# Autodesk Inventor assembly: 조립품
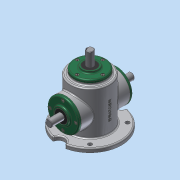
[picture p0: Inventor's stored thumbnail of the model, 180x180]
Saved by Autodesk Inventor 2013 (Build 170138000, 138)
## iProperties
Created: 2018-04
Part Number: 조립품
Document SubType Name: Assembly
Designer: dgall
Author: dgall
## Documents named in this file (16)
- C:\Users\dgall\Desktop\480407V1029\조립품.iam
- C:\Users\dgall\Desktop\480407V1029\메인 베벨기어.ipt
- C:\Users\dgall\Desktop\480407V1029\메인 축.ipt
- 메인 축.ipt
- C:\Users\dgall\Desktop\480407V1029\베어링 6203.ipt
- C:\Users\dgall\Desktop\480407V1029\본체1.ipt
- C:\Users\dgall\Desktop\480407V1029\볼트 M4.ipt
- 볼트 M4.ipt
- C:\Users\dgall\Desktop\480407V1029\서브 베벨기어.ipt
- C:\Users\dgall\Desktop\480407V1029\서브 축.ipt
- 서브 축.ipt
- C:\Users\dgall\Desktop\480407V1029\오일 실.ipt
- 오일 실.ipt
- C:\Users\dgall\Desktop\480407V1029\커버.ipt
- C:\Users\dgall\Desktop\480407V1029\키 4x4.ipt
- C:\Users\dgall\Desktop\480407V1029\키 5x5.ipt
